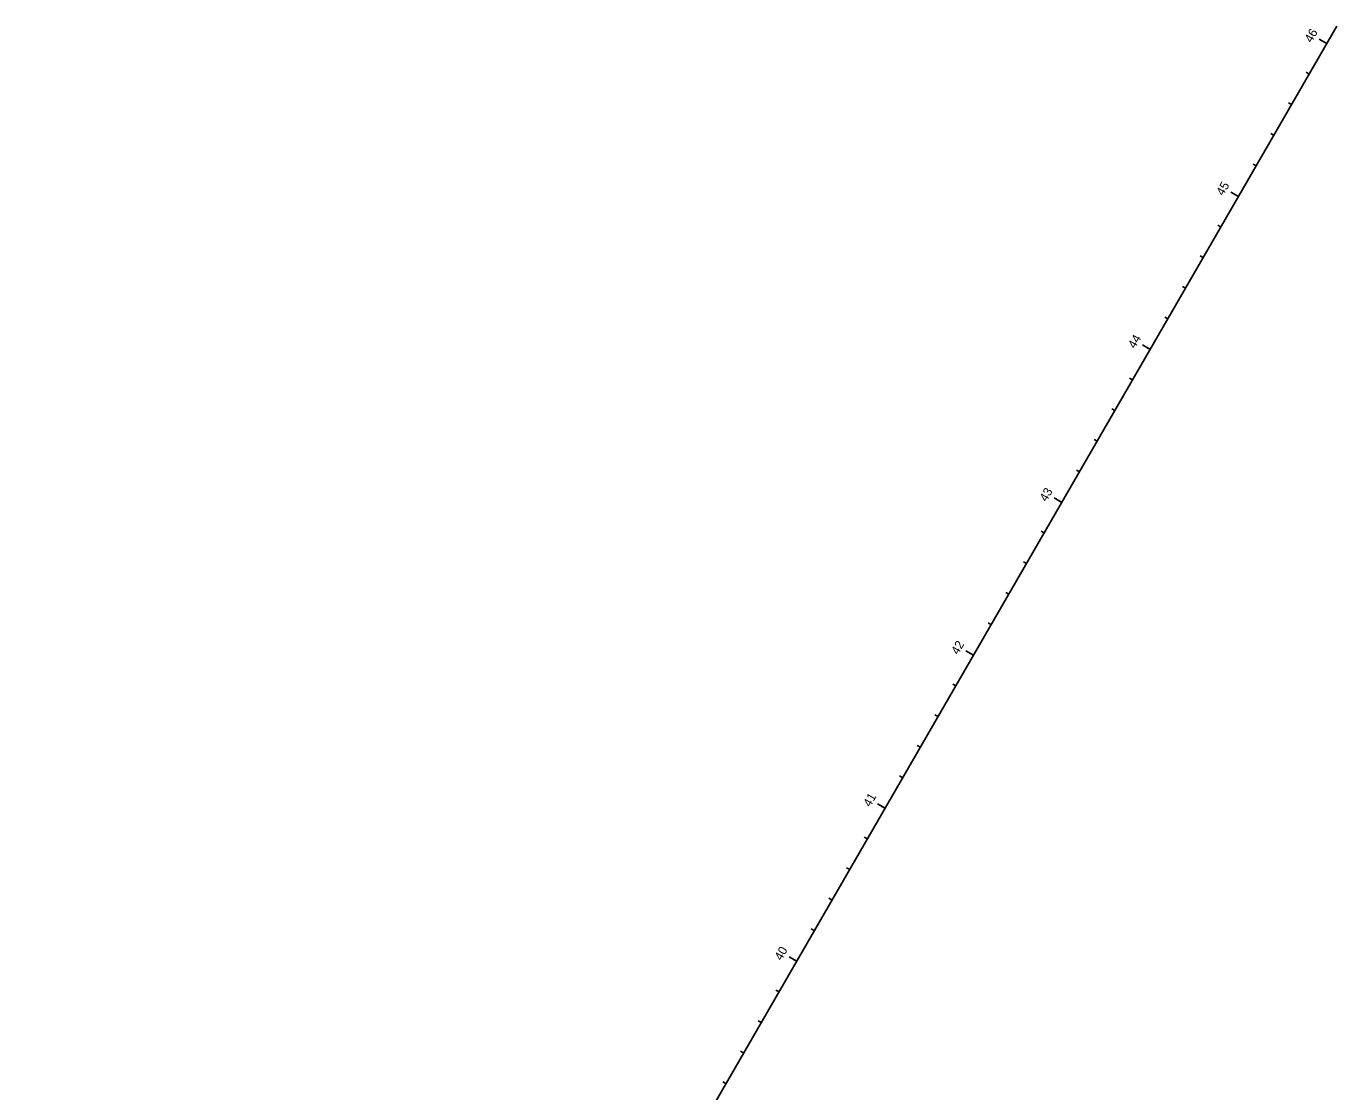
# Model space of a CAD drawing. Extents: x 2005660 to 2007493, y 401364 to 404817.
# Drawn here: x 2006751 to 2007493, y 403182 to 403785 of the extents above; entities that cross this region are included whole.
import ezdxf

# ---------------------------------------------------------------- set-up
doc = ezdxf.new("R2010")
doc.units = 0
for name, color, linetype in [('ConstLines', 7, 'Continuous'), ('CurbBack', 7, 'Continuous'), ('PavtAsphalt', 7, 'Continuous'), ('PavtAsphalt_ep', 7, 'Continuous'), ('PavtMilling', 7, 'Continuous'), ('ScratchEle_dp', 7, 'Continuous'), ('TextAlgnTicks5000', 7, 'Continuous'), ('TrafSeparator', 7, 'Continuous')]:
    doc.layers.add(name, color=color, linetype=linetype)

msp = doc.modelspace()

# ---------------------------------------------------------------- linework, layer by layer
at = {"layer": 'PavtAsphalt'}
for p, q in [((2007487.64, 403775.31), (2007483.31, 403777.81)), ((2007477.63, 403757.99), (2007475.9, 403758.99)), ((2007467.63, 403740.67), (2007465.9, 403741.67)), ((2007457.63, 403723.35), (2007455.9, 403724.35)), ((2007447.62, 403706.03), (2007445.89, 403707.03)), ((2007437.62, 403688.71), (2007433.29, 403691.21)), ((2007427.62, 403671.39), (2007425.89, 403672.39)), ((2007417.62, 403654.08), (2007415.88, 403655.08)), ((2007407.61, 403636.76), (2007405.88, 403637.76)), ((2007397.61, 403619.44), (2007395.88, 403620.44)), ((2007387.61, 403602.12), (2007383.28, 403604.62)), ((2007377.61, 403584.8), (2007375.87, 403585.8)), ((2007367.6, 403567.48), (2007365.87, 403568.48)), ((2007357.6, 403550.16), (2007355.87, 403551.16)), ((2007347.6, 403532.84), (2007345.87, 403533.84)), ((2007337.59, 403515.52), (2007333.27, 403518.02)), ((2007327.59, 403498.21), (2007325.86, 403499.21)), ((2007317.59, 403480.89), (2007315.86, 403481.89)), ((2007307.59, 403463.57), (2007305.86, 403464.57)), ((2007297.58, 403446.25), (2007295.85, 403447.25)), ((2007287.58, 403428.93), (2007283.25, 403431.43)), ((2007277.58, 403411.61), (2007275.85, 403412.61)), ((2007267.58, 403394.29), (2007265.84, 403395.29)), ((2007257.57, 403376.97), (2007255.84, 403377.97)), ((2007247.57, 403359.65), (2007245.84, 403360.65)), ((2007237.57, 403342.33), (2007233.24, 403344.84)), ((2007227.57, 403325.02), (2007225.83, 403326.02)), ((2007217.56, 403307.7), (2007215.83, 403308.7)), ((2007207.56, 403290.38), (2007205.83, 403291.38)), ((2007197.56, 403273.06), (2007195.83, 403274.06)), ((2007187.55, 403255.74), (2007183.22, 403258.24)), ((2007177.55, 403238.42), (2007175.82, 403239.42)), ((2007167.55, 403221.1), (2007165.82, 403222.1)), ((2007157.55, 403203.78), (2007155.81, 403204.78)), ((2007147.54, 403186.46), (2007145.81, 403187.46))]:
    msp.add_line(p, q, dxfattribs=at)
at = {"layer": 'PavtAsphalt_ep'}
msp.add_line((2006751.44, 402500.64), (2007493.27, 403785.06), dxfattribs=at)
at = {"layer": 'ScratchEle_dp'}
for p, q in [((2007487.64, 403775.31), (2007485.9, 403776.31)), ((2007437.62, 403688.71), (2007433.29, 403691.21)), ((2007387.61, 403602.12), (2007385.88, 403603.12)), ((2007337.59, 403515.52), (2007335.86, 403516.52)), ((2007287.58, 403428.93), (2007285.85, 403429.93)), ((2007237.57, 403342.33), (2007235.84, 403343.33)), ((2007187.55, 403255.74), (2007183.22, 403258.24))]:
    msp.add_line(p, q, dxfattribs=at)
at = {"layer": 'TextAlgnTicks5000'}
msp.add_line((2007187.55, 403255.74), (2007185.82, 403256.74), dxfattribs=at)
at = {"layer": 'TrafSeparator'}
for p, q in [((2007487.64, 403775.31), (2007485.9, 403776.31)), ((2007387.61, 403602.12), (2007385.88, 403603.12)), ((2007287.58, 403428.93), (2007285.85, 403429.93)), ((2007187.55, 403255.74), (2007183.22, 403258.24))]:
    msp.add_line(p, q, dxfattribs=at)

# ---------------------------------------------------------------- texts
at = {"layer": 'ConstLines'}
for s, p in [('45', (2007428.97, 403688.74)), ('40', (2007178.93, 403255.8))]:
    msp.add_text(s, height=4.98, rotation=59.99111, dxfattribs=at).set_placement(p)
at = {"layer": 'CurbBack'}
msp.add_text('40', height=4.98, rotation=59.99111, dxfattribs=at).set_placement((2007178.93, 403255.8))
at = {"layer": 'PavtMilling'}
for s, p in [('46', (2007479, 403775.36)), ('45', (2007428.97, 403688.74)), ('44', (2007379, 403602.21)), ('43', (2007328.94, 403515.53)), ('42', (2007278.92, 403428.94)), ('41', (2007229.14, 403342.73)), ('40', (2007178.93, 403255.8))]:
    msp.add_text(s, height=4.98, rotation=59.99111, dxfattribs=at).set_placement(p)

doc.saveas('drawing.dxf')
